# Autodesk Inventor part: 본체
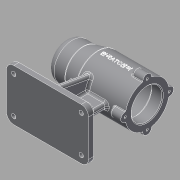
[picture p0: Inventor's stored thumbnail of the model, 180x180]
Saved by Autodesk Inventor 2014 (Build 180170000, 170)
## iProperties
Created: 2019-07
Part Number: 본체
Material: Generic
Document SubType Name: Modeling
Designer: kb542-5
Density: 1 g/cm^3
Appearance: Default
Mass: 238.662 g
Surface Area: 654.083 cm^2
Volume: 238.662 cm^3
Author: kb542-5
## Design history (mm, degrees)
sketch "스케치1"
  geometry: 1 further point
sketch "스케치2"
  geometry: L1 (-56, 0)-(56, 0); L2 (-56, 0)-(-56, 25); L3 (-56, 25)-(-31, 25); L4 (-31, 25)-(-11, 30); L5 (-11, 30)-(56, 30); L6 (56, 21)-(41, 21); L7 (41, 21)-(41, 24); L8 (41, 24)-(-13, 24); L9 (-13, 24)-(-13, 21); L10 (-13, 21)-(-25, 21); L11 (-25, 21)-(-25, 17.5); L12 (-25, 17.5)-(-43, 17.5); L13 (-43, 17.5)-(-43, 16); L14 (-43, 16)-(-47, 16); L15 (-47, 16)-(-47, 10.5); L16 (-47, 10.5)-(-50, 10.5); L17 (-50, 10.5)-(-50, 0); L18 (56, 21)-(56, 30); 2 further points
  constraints: 36 end point, 12 parallel, 3 perpendicular, 2 horizontal, 1 coincident, 1 midpoint, 1 point on line, 1 vertical alignment
  dimensions: "d0" = 112 distance of L1.start L1.end; "d1" = 60 diameter of L5 L1; "d2" = 21 diameter of L16 L1; "d3" = 32 diameter of L14 L1; "d4" = 35 diameter of L12 L1; "d5" = 42 diameter of L10 L1; "d6" = 48 diameter of L8 L1; "d7" = 42 diameter of L6 L1; "d8" = 50 diameter of L3 L1; "d9" = 25 distance of L3.end L2.end; "d10" = 45 horizontal distance of L4.end L2.end; "d11" = 15 distance of L6.start L6.end; "d12" = 54 distance of L7.end L8.end; "d13" = 12 distance of L9.end L10.end; "d14" = 18 distance of L11.end L12.end; "d15" = 4 distance of L13.end L14.end; "d16" = 3 distance of L15.end L16.end
revolve "회전1" sketch "스케치2" stored, may be unused: angle "d17" = 90 deg
sketch "스케치3"
  geometry: A1 r 30 centre (0, 0) between (0, 30) and (-5.97, 29.4) reference; A2 r 6 centre (0, 30) between (5.97, 29.4) and (-5.97, 29.4); 1 further point
  constraints: 5 point on circle, 1 centre point, 1 vertical alignment
  dimensions: "d18" = 6 radius of A2
extrude "돌출1" join sketch "스케치3" distance "d19" = 16; taper "d20" = 0 deg
fillet "모깎기1" dims "d21" = 3
fillet "모깎기2" dims "d22" = 1, "d26" = 3
node "작업 평면1"
sketch "스케치4"
  geometry: L1 (56, 35)-(-56, 35); L2 (-56, 35)-(-56, -35); L3 (-56, -35)-(56, -35); L4 (56, -35)-(56, 35); L5 (56, 35)-(-56, -35); L6 (-56, 35)-(56, -35); 1 further point
  constraints: 12 end point, 2 midpoint, 2 parallel, 1 horizontal, 1 perpendicular
  dimensions: "d28" = 112 distance of L2.end L3.end; "d29" = 70 distance of L1.end L2.end
extrude "돌출2" join sketch "스케치4" distance "d30" = 10; taper "d31" = 0 deg
fillet "모깎기3" dims "d32" = 10
sketch "스케치5"
  geometry: L1 (-22.666, 19.654)-(-70, 28); L2 (-70, 35)-(-70, 25) reference; L3 (-22.666, -19.654)-(-70, -28); L4 (-70, -25)-(-70, -35) reference; L5 (-70, -25)-(-70, 25) reference; L6 (0, 0)-(-70, 0); A1 r 30 centre (0, 0) between (-22.666, 19.654) and (-22.666, -19.654) reference; 1 further point
  constraints: 6 end point, 2 point on circle, 2 point on line, 1 midpoint, 1 other
  dimensions: "d33" = 7 distance of L1.end L2.start; "d34" = 100 deg angle of L2 L1
extrude "돌출3" join sketch "스케치5" stored distance "d35" = 8; taper "d36" = 0 deg
sketch "스케치6"
  geometry: L1 (-11, -30)-(39, -30) reference; L2 (31, -30)-(31, -70); L3 (46, -70)-(-46, -70) reference; L4 (56, -70)-(56, -80) reference; L5 (-31, -25)-(-11, -30) reference; L6 (-20.57, -27.607)-(-36, -70); L7 (-56, -80)-(-56, -70) reference; 1 further point
  constraints: 4 end point, 4 point on line, 1 vertical
  dimensions: "d37" = 25 distance between parallel lines of L4 L2; "d38" = 20 distance from line of L6.end L7; "d39" = 110 deg angle of L3 L6
feature "리브1" dims "d40" = 1, "d41" = 8, "d42" = 0, "d43" = 0, "d44" = 1, "d45" = 1
feature "리브2" dims "d46" = 1, "d47" = 8, "d48" = 0, "d49" = 0, "d50" = 1, "d51" = 1
sketch "스케치7"
  geometry: L1 (46, 35)-(-46, 35) reference; L2 (-56, 25)-(-56, -25) reference; L3 (46, 35)-(-46, 35) reference; L4 (56, -25)-(56, 25) reference; L5 (-46, -35)-(46, -35) reference; A1 r 10 centre (-46, 25) between (-46, 35) and (-56, 25) reference; A2 r 10 centre (46, 25) between (56, 25) and (46, 35) reference; A3 r 10 centre (46, -25) between (46, -35) and (56, -25) reference; A4 r 10 centre (-46, -25) between (-56, -25) and (-46, -35) reference; 5 further points
  constraints: 4 coincident
hole "구멍1" sketch "스케치7" at (-46, 25), (-46, -25), (46, -25), (46, 25) diameter "d52" = 6; stored, may be unused: countersink angle "d56" = 90 deg, drill point angle "d58" = 118 deg; dims "d53" = 6, "d54" = 4, "d55" = 2, "d57" = 8
chamfer "모따기1" distance "d59" = 3; stored, may be unused: second distance "d60" = 2, angle "d61" = 45 deg
chamfer "모따기2" distance "d62" = 1; stored, may be unused: second distance "d63" = 2, angle "d64" = 45 deg
fillet "모깎기4" dims "d65" = 0.3, "d66" = 3
fillet "모깎기5" dims "d67" = 10, "d68" = 3
fillet "모깎기6" dims "d69" = 3
sketch "스케치8"
  geometry: C1 r 22 at (0, -30) reference; A1 r 6 centre (0, -60) between (-5.998, -60.171) and (5.998, -60.171) reference; A2 r 1 centre (6.997, -60.2) between (6.771, -59.226) and (5.998, -60.171) reference; A3 r 30 centre (0, -30) between (6.771, -59.226) and (29.226, -36.771) reference; A4 r 1 centre (30.2, -36.997) between (30.171, -35.998) and (29.226, -36.771) reference; A5 r 6 centre (30, -30) between (30.171, -35.998) and (30.171, -24.002) reference; A6 r 1 centre (30.2, -23.003) between (29.226, -23.229) and (30.171, -24.002) reference; A7 r 30 centre (0, -30) between (29.226, -23.229) and (6.771, -0.774) reference; A8 r 1 centre (6.997, 0.2) between (5.998, 0.171) and (6.771, -0.774) reference; A9 r 6 centre (0, 0) between (5.998, 0.171) and (-5.998, 0.171) reference; A10 r 1 centre (-6.997, 0.2) between (-6.771, -0.774) and (-5.998, 0.171) reference; A11 r 30 centre (0, -30) between (-6.771, -0.774) and (-29.226, -23.229) reference; A12 r 1 centre (-30.2, -23.003) between (-30.171, -24.002) and (-29.226, -23.229) reference; A13 r 6 centre (-30, -30) between (-30.171, -24.002) and (-30.171, -35.998) reference; A14 r 1 centre (-30.2, -36.997) between (-29.226, -36.771) and (-30.171, -35.998) reference; A15 r 30 centre (0, -30) between (-29.226, -36.771) and (-6.771, -59.226) reference; A16 r 1 centre (-6.997, -60.2) between (-5.998, -60.171) and (-6.771, -59.226) reference; 5 further points
  constraints: 4 coincident
hole "구멍2" sketch "스케치8" at (0, 0), (-30, -30), (30, -30), (0, -60) diameter "d70" = 3.242; stored, may be unused: countersink angle "d74" = 90 deg, drill point angle "d76" = 118 deg; dims "d71" = 8, "d72" = 4, "d73" = 2, "d75" = 11
node "작업 평면2"
sketch "스케치9"
  geometry: L1 (56, 6.771)-(56, 29.226) reference; 2 further points
  constraints: 1 horizontal alignment, 1 other
  dimensions: "d78" = 42 distance from line of L1 point (14, 0)
feature "엠보싱1" sketch "스케치9" dims "d0" = 112, "d1" = 60, "d2" = 21, "d3" = 32, "d4" = 35, "d5" = 42, "d6" = 48, "d7" = 42, "d8" = 50, "d9" = 25, "d10" = 45, "d11" = 15, "d12" = 54, "d13" = 12, "d14" = 18, "d15" = 4, "d16" = 3, "d79" = 0.5, "d80" = 0
node "솔리드1"
pattern_circular "원형 패턴1" dims "d24" = 360 deg
node "투영된 루프1"
node "투영된 루프2"
